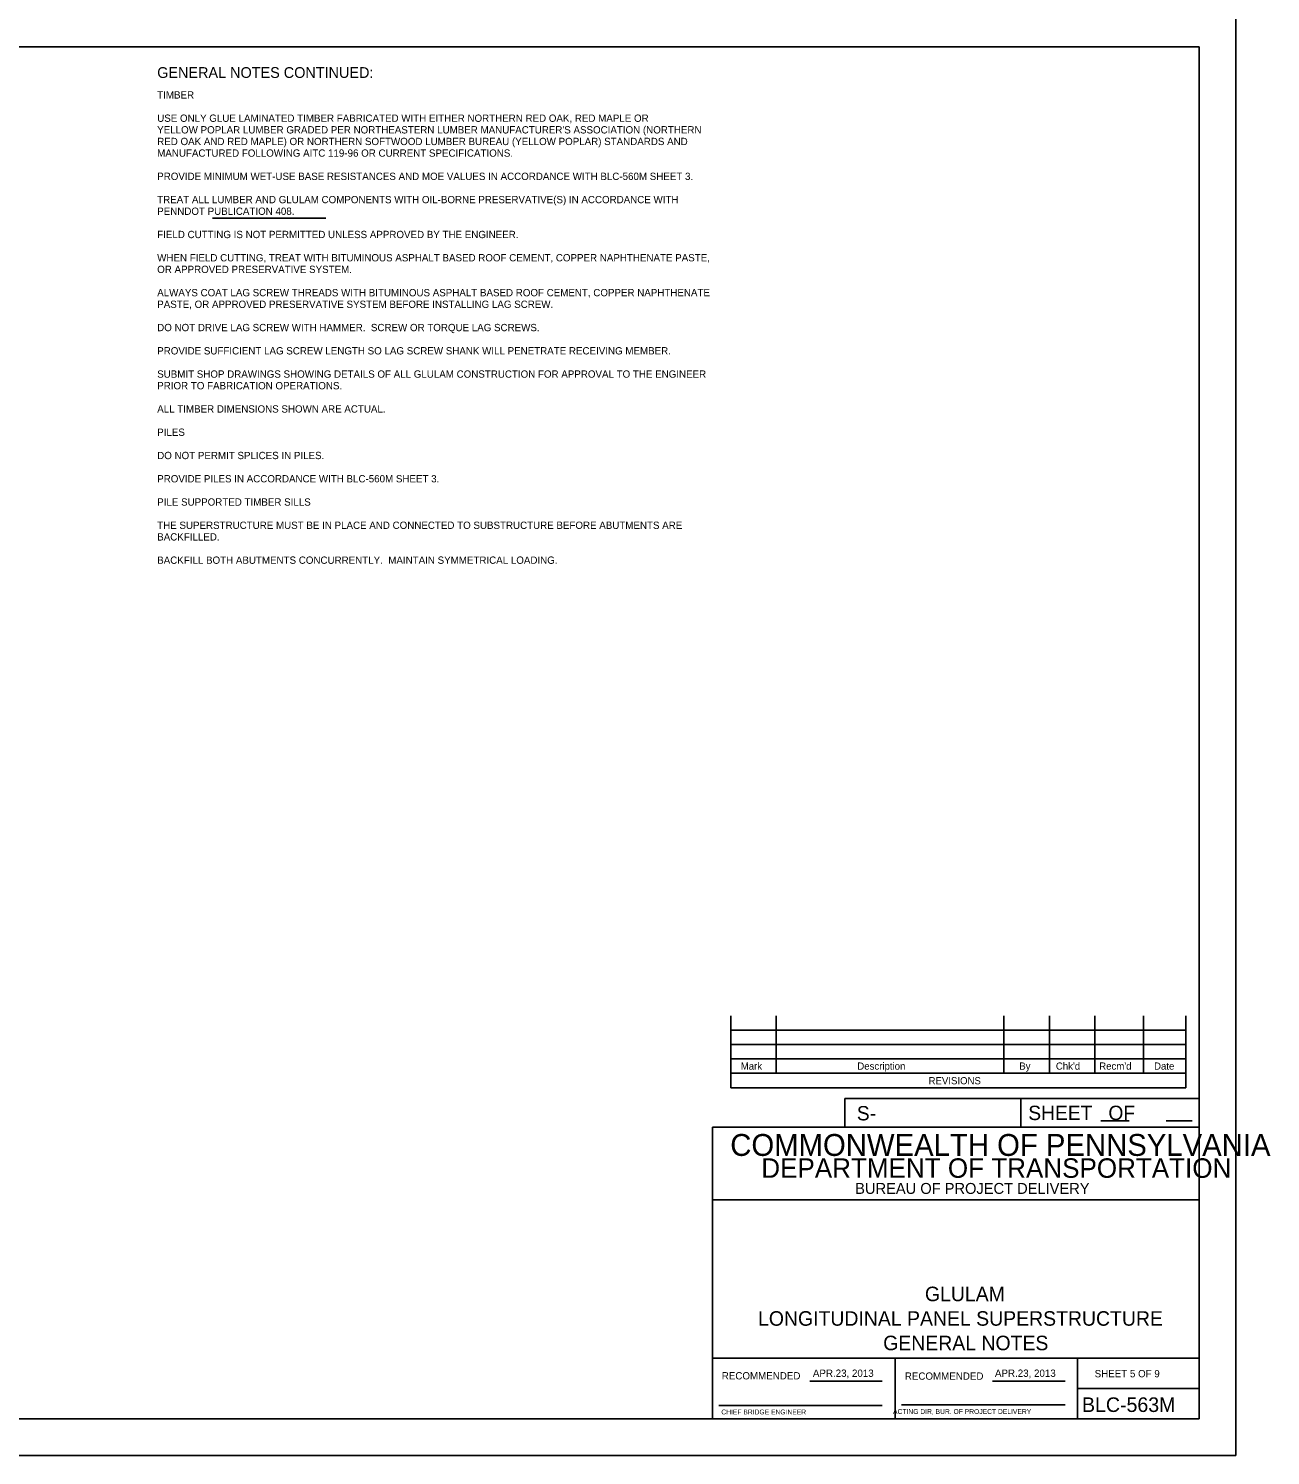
# Model space of a CAD drawing. Extents: x 638268 to 640277, y 295465 to 298435.
# Drawn here: x 638780 to 639291, y 295465 to 296052 of the extents above; entities that cross this region are included whole.
import ezdxf

# ---------------------------------------------------------------- set-up
doc = ezdxf.new("R2010")
doc.units = 0
for name, color, linetype in [('1', 7, 'Continuous'), ('2', 7, 'Continuous'), ('4', 7, 'Continuous'), ('PLT-BNDY', 7, 'Continuous')]:
    doc.layers.add(name, color=color, linetype=linetype)

msp = doc.modelspace()

# ---------------------------------------------------------------- linework, layer by layer
at = {"layer": '2'}
for p, q in [((638475.46, 296044.46), (639261.46, 296044.46)), ((639261.46, 296044.46), (639261.46, 295480.46)), ((638902.59, 295973.95), (638855.93, 295973.95)), ((639068.92, 295646.15), (639068.92, 295616.62)), ((639087.62, 295646.15), (639087.62, 295622.53)), ((639181.13, 295646.15), (639181.13, 295622.53)), ((639199.83, 295646.15), (639199.83, 295622.53)), ((639218.53, 295646.15), (639218.53, 295622.53)), ((639238.59, 295646.15), (639238.59, 295622.53)), ((639255.94, 295646.15), (639255.94, 295616.62)), ((639255.94, 295640.24), (639068.92, 295640.24)), ((639255.94, 295634.34), (639068.92, 295634.34)), ((639255.94, 295628.43), (639068.92, 295628.43)), ((639255.94, 295622.53), (639068.92, 295622.53)), ((639255.94, 295616.62), (639068.92, 295616.62)), ((639261.46, 295612.11), (639115.78, 295612.11)), ((639115.78, 295612.11), (639115.78, 295600.46)), ((639188.09, 295612.11), (639188.09, 295600.46)), ((639261.46, 295612.11), (639261.46, 295600.46)), ((639220.95, 295603), (639232.6, 295603)), ((639247.83, 295603), (639258.56, 295603)), ((639261.46, 295600.46), (639061.46, 295600.46)), ((639061.46, 295600.46), (639061.46, 295480.46)), ((639261.46, 295600.46), (639115.78, 295600.46)), ((639261.46, 295570.46), (639061.46, 295570.46)), ((639261.46, 295505.46), (639061.46, 295505.46)), ((639136.46, 295480.46), (639136.46, 295505.46)), ((639211.46, 295505.46), (639211.46, 295480.46)), ((639101.42, 295495.96), (639131.19, 295495.96)), ((639176.42, 295495.96), (639206.33, 295495.96)), ((639211.46, 295492.96), (639261.46, 295492.96)), ((639063.96, 295485.96), (639131.19, 295485.96)), ((639139.08, 295486.33), (639206.33, 295486.33)), ((639261.46, 295480.46), (638475.46, 295480.46))]:
    msp.add_line(p, q, dxfattribs=at)
at = {"layer": 'PLT-BNDY'}
msp.add_lwpolyline([(638435.46, 296059.46), (639276.46, 296059.46), (639276.46, 295465.46), (638435.46, 295465.46)], close=True, dxfattribs=at)

# ---------------------------------------------------------------- texts
at = {"layer": '1'}
msp.add_text('SHEET 5 OF 9', height=3, dxfattribs=at).set_placement((639218.45, 295497.58))
at = {"layer": '2'}
for s, height, p in [('GENERAL NOTES CONTINUED:', 4.4292, (638833.23, 296031.66)), ('TIMBER', 3, (638833.23, 296023.17)), ('USE ONLY GLUE LAMINATED TIMBER FABRICATED WITH EITHER NORTHERN RED OAK, RED MAPLE OR ', 3, (638833.23, 296013.61)), ("YELLOW POPLAR LUMBER GRADED PER NORTHEASTERN LUMBER MANUFACTURER'S ASSOCIATION (NORTHERN", 3, (638833.23, 296008.83)), ('RED OAK AND RED MAPLE) OR NORTHERN SOFTWOOD LUMBER BUREAU (YELLOW POPLAR) STANDARDS AND ', 3, (638833.23, 296004.05)), ('MANUFACTURED FOLLOWING AITC 119-96 OR CURRENT SPECIFICATIONS.', 3, (638833.23, 295999.27)), ('PROVIDE MINIMUM WET-USE BASE RESISTANCES AND MOE VALUES IN ACCORDANCE WITH BLC-560M SHEET 3.', 3, (638833.23, 295989.71)), ('TREAT ALL LUMBER AND GLULAM COMPONENTS WITH OIL-BORNE PRESERVATIVE(S) IN ACCORDANCE WITH', 3, (638833.23, 295980.15)), ('PENNDOT PUBLICATION 408.', 3, (638833.23, 295975.37)), ('FIELD CUTTING IS NOT PERMITTED UNLESS APPROVED BY THE ENGINEER.', 3, (638833.23, 295965.81)), ('WHEN FIELD CUTTING, TREAT WITH BITUMINOUS ASPHALT BASED ROOF CEMENT, COPPER NAPHTHENATE PASTE, ', 3, (638833.23, 295956.25)), ('OR APPROVED PRESERVATIVE SYSTEM.', 3, (638833.23, 295951.47)), ('ALWAYS COAT LAG SCREW THREADS WITH BITUMINOUS ASPHALT BASED ROOF CEMENT, COPPER NAPHTHENATE', 3, (638833.23, 295941.9)), ('PASTE, OR APPROVED PRESERVATIVE SYSTEM BEFORE INSTALLING LAG SCREW.', 3, (638833.23, 295937.12)), ('DO NOT DRIVE LAG SCREW WITH HAMMER.  SCREW OR TORQUE LAG SCREWS.', 3, (638833.23, 295927.56)), ('PROVIDE SUFFICIENT LAG SCREW LENGTH SO LAG SCREW SHANK WILL PENETRATE RECEIVING MEMBER.', 3, (638833.23, 295918)), ('SUBMIT SHOP DRAWINGS SHOWING DETAILS OF ALL GLULAM CONSTRUCTION FOR APPROVAL TO THE ENGINEER ', 3, (638833.23, 295908.44)), ('PRIOR TO FABRICATION OPERATIONS.', 3, (638833.23, 295903.66)), ('ALL TIMBER DIMENSIONS SHOWN ARE ACTUAL.', 3, (638833.23, 295894.1)), ('PILES', 3, (638833.23, 295884.54)), ('DO NOT PERMIT SPLICES IN PILES.', 3, (638833.23, 295874.97)), ('PROVIDE PILES IN ACCORDANCE WITH BLC-560M SHEET 3.', 3, (638833.23, 295865.41)), ('PILE SUPPORTED TIMBER SILLS', 3, (638833.23, 295855.85)), ('THE SUPERSTRUCTURE MUST BE IN PLACE AND CONNECTED TO SUBSTRUCTURE BEFORE ABUTMENTS ARE ', 3, (638833.23, 295846.29)), ('BACKFILLED.', 3, (638833.23, 295841.51)), ('BACKFILL BOTH ABUTMENTS CONCURRENTLY.  MAINTAIN SYMMETRICAL LOADING.', 3, (638833.23, 295831.95)), ('Mark', 2.952, (639073.02, 295624.03)), ('Description', 2.9523, (639120.92, 295624.03)), ('By', 2.952, (639187.49, 295624.03)), ("Chk'd", 2.952, (639202.52, 295624.03)), ("Recm'd", 2.953, (639220.33, 295624.03)), ('Date', 2.952, (639242.86, 295624.03)), ('REVISIONS', 2.952, (639150.2, 295618.01)), ('S-', 5.905, (639120.73, 295603.17)), ('COMMONWEALTH OF PENNSYLVANIA', 9, (639068.71, 295588.58)), ('DEPARTMENT OF TRANSPORTATION', 8.0002, (639081.46, 295579.58)), ('BUREAU OF PROJECT DELIVERY', 4.5, (639120.05, 295572.96)), ('GENERAL NOTES', 5.9714, (639131.55, 295508.71)), ('APR.23, 2013', 3, (639102.67, 295497.77)), ('APR.23, 2013', 3, (639177.48, 295497.77)), ('BLC-563M', 6, (639213.27, 295483.33)), ('CHIEF BRIDGE ENGINEER', 2.0002, (639065.05, 295482.33)), ('  ACTING DIR, BUR. OF PROJECT DELIVERY', 2.0002, (639134.07, 295482.51))]:
    msp.add_text(s, height=height, dxfattribs=at).set_placement(p)
for s, height, p in [('SHEET   OF', 5.907, (639191.18, 295603.31)), ('RECOMMENDED', 3, (639065.23, 295496.71)), ('RECOMMENDED', 3, (639140.44, 295496.58))]:
    msp.add_text(s, height=height, rotation=360, dxfattribs=at).set_placement(p)
at = {"layer": '4'}
for s, height, p in [('GLULAM', 5.971, (639148.71, 295528.86)), ('LONGITUDINAL PANEL SUPERSTRUCTURE', 5.9714, (639080.13, 295518.78))]:
    msp.add_text(s, height=height, dxfattribs=at).set_placement(p)

doc.saveas('drawing.dxf')
